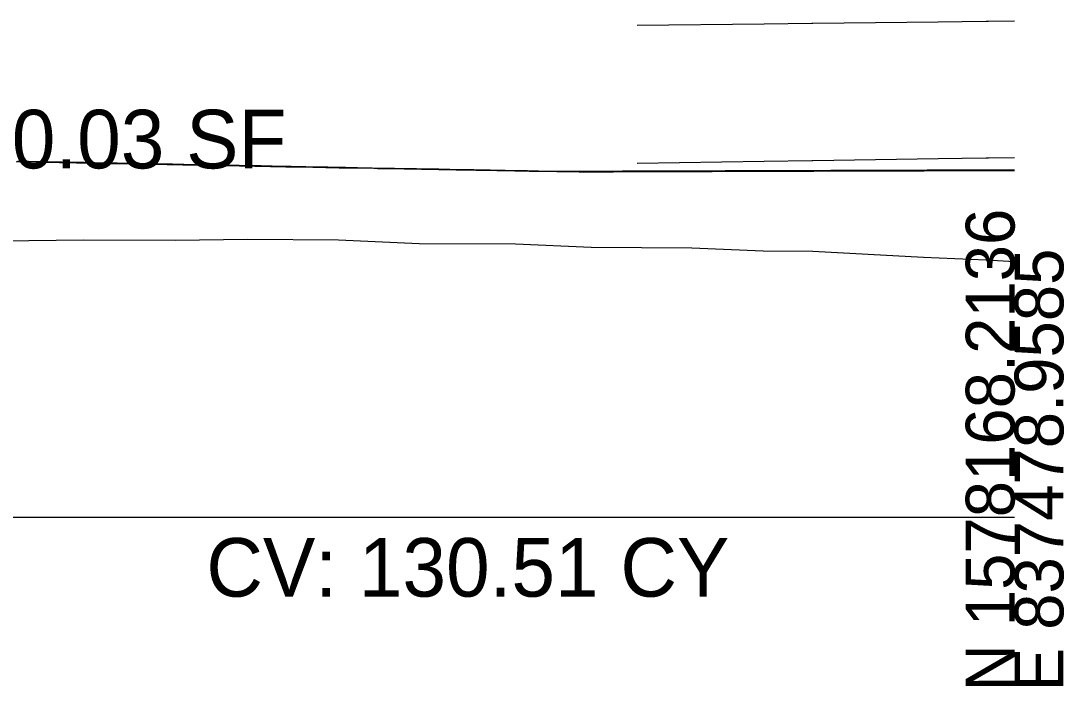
# Model space of a CAD drawing. Extents: x -26 to 303, y -16 to 6048.
# Drawn here: x 243 to 302.8, y 5490.3 to 5528.5 of the extents above; entities that cross this region are included whole.
import ezdxf

# ---------------------------------------------------------------- set-up
doc = ezdxf.new("R2010")
doc.units = 0
for name, color, linetype in [('CONST_LV3', 7, 'Continuous'), ('DTM_P_FINISHED_GRADE2', 7, 'Continuous'), ('DTM_X_GROUND', 7, 'Continuous'), ('XS_CELL', 7, 'Continuous'), ('XS_M_SHAPES_EARTHWORK', 7, 'Continuous'), ('XS_P_GROUND', 7, 'Continuous'), ('XS_SHEET_EW_TX_AREA', 7, 'Continuous'), ('XS_SHEET_EW_TX_VOLUME', 7, 'Continuous')]:
    doc.layers.add(name, color=color, linetype=linetype)

msp = doc.modelspace()

# ---------------------------------------------------------------- linework, layer by layer
at = {"layer": 'CONST_LV3'}
for points in [[(278.373, 5528.214), (285.642, 5528.296), (288.373, 5528.327), (288.404, 5528.327), (288.414, 5528.327), (288.44, 5528.328), (295.619, 5528.411), (298.374, 5528.443), (298.435, 5528.443), (298.455, 5528.444), (298.506, 5528.444), (300, 5528.462)], [(278.373, 5520.307), (285.642, 5520.418), (288.373, 5520.459), (288.404, 5520.46), (288.414, 5520.46), (288.44, 5520.46), (295.619, 5520.569), (298.374, 5520.61), (298.435, 5520.611), (298.455, 5520.611), (298.506, 5520.612), (300, 5520.634)]]:
    msp.add_lwpolyline(points, dxfattribs=at)
at = {"layer": 'DTM_P_FINISHED_GRADE2'}
msp.add_lwpolyline([(243.02, 5520.399), (243.352, 5520.393), (243.522, 5520.39), (243.654, 5520.387), (244.12, 5520.378), (244.289, 5520.375), (244.755, 5520.366), (244.923, 5520.363), (245.391, 5520.354), (245.558, 5520.351), (245.606, 5520.35), (245.624, 5520.35), (246.092, 5520.341), (246.193, 5520.339), (246.328, 5520.336), (246.378, 5520.335), (246.495, 5520.333), (246.779, 5520.328), (246.827, 5520.327), (247.16, 5520.32), (247.324, 5520.317), (247.462, 5520.315), (247.625, 5520.312), (248.097, 5520.303), (248.259, 5520.299), (248.732, 5520.291), (248.893, 5520.287), (249.367, 5520.279), (249.528, 5520.275), (250.001, 5520.267), (250.114, 5520.264), (250.588, 5520.255), (250.636, 5520.255), (250.968, 5520.248), (251.094, 5520.246), (251.238, 5520.243), (251.271, 5520.243), (251.647, 5520.235), (251.806, 5520.232), (251.905, 5520.231), (252.382, 5520.222), (252.54, 5520.219), (253.018, 5520.21), (253.224, 5520.206), (253.857, 5520.194), (253.946, 5520.192), (253.963, 5520.192), (254.07, 5520.19), (254.342, 5520.185), (254.395, 5520.184), (254.727, 5520.177), (254.928, 5520.174), (255.559, 5520.162), (255.744, 5520.158), (256.326, 5520.147), (256.446, 5520.145), (256.83, 5520.138), (257.131, 5520.132), (257.233, 5520.13), (258.203, 5520.112), (258.4, 5520.108), (258.731, 5520.102), (259.027, 5520.096), (259.669, 5520.084), (259.82, 5520.081), (259.852, 5520.081), (259.904, 5520.08), (260.881, 5520.061), (260.94, 5520.06), (261.039, 5520.058), (261.539, 5520.049), (261.735, 5520.045), (261.844, 5520.043), (262.016, 5520.04), (262.211, 5520.036), (262.506, 5520.031), (262.835, 5520.025), (263.482, 5520.013), (263.777, 5520.007), (264.753, 5519.989), (264.851, 5519.987), (264.92, 5519.986), (265.049, 5519.983), (266.024, 5519.965), (266.32, 5519.96), (266.644, 5519.954), (267.293, 5519.942), (267.467, 5519.938), (268.439, 5519.92), (268.562, 5519.918), (269.132, 5519.908), (269.229, 5519.906), (269.426, 5519.902), (269.83, 5519.895), (270.037, 5519.891), (270.358, 5519.885), (270.443, 5519.883), (271.101, 5519.871), (271.393, 5519.866), (272.085, 5519.853), (272.18, 5519.851), (272.466, 5519.846), (272.664, 5519.842), (272.704, 5519.842), (272.956, 5519.843), (273.937, 5519.825), (274.09, 5519.825), (274.407, 5519.82), (274.415, 5519.82), (274.548, 5519.82), (275.21, 5519.808), (275.304, 5519.808), (275.44, 5519.807), (275.642, 5519.808), (276.485, 5519.81), (276.993, 5519.812), (277.019, 5519.812), (277.355, 5519.813), (277.793, 5519.815), (278.103, 5519.816), (278.764, 5519.818), (279.099, 5519.819), (279.122, 5519.819), (279.166, 5519.819), (279.212, 5519.82), (280.301, 5519.823), (280.524, 5519.824), (280.861, 5519.825), (281.954, 5519.829), (281.963, 5519.829), (282.036, 5519.829), (282.179, 5519.829), (282.51, 5519.83), (282.661, 5519.831), (283.383, 5519.833), (283.643, 5519.834), (283.653, 5519.834), (284.737, 5519.838), (284.811, 5519.838), (284.842, 5519.838), (285.189, 5519.839), (286.24, 5519.843), (287.055, 5519.845), (287.406, 5519.846), (287.436, 5519.846), (287.665, 5519.847), (288.016, 5519.848), (289.092, 5519.852), (289.217, 5519.852), (289.234, 5519.852), (289.446, 5519.853), (290.523, 5519.856), (290.881, 5519.857), (291.953, 5519.861), (292.312, 5519.862), (292.689, 5519.863), (292.74, 5519.863), (292.743, 5519.863), (293.381, 5519.865), (293.708, 5519.866), (294.77, 5519.87), (294.809, 5519.87), (295.178, 5519.871), (296.229, 5519.874), (296.48, 5519.875), (296.488, 5519.875), (296.608, 5519.876), (297.552, 5519.879), (297.665, 5519.879), (298.039, 5519.88), (299.094, 5519.883), (299.27, 5519.884), (299.472, 5519.884), (300, 5519.886)], dxfattribs=at)
at = {"layer": 'DTM_X_GROUND'}
for points in [[(243.02, 5520.399), (243.352, 5520.393), (243.49, 5520.39), (243.535, 5520.389), (243.622, 5520.388), (243.654, 5520.387), (244.032, 5520.38), (244.17, 5520.377), (244.257, 5520.376), (244.289, 5520.375), (244.668, 5520.368), (244.804, 5520.365), (244.892, 5520.363), (244.923, 5520.363), (245.303, 5520.356), (245.439, 5520.353), (245.527, 5520.351), (245.558, 5520.351), (245.606, 5520.35), (245.987, 5520.343), (246.005, 5520.342), (246.074, 5520.341), (246.162, 5520.339), (246.193, 5520.339), (246.328, 5520.336), (246.378, 5520.335), (246.495, 5520.333), (246.691, 5520.329), (246.708, 5520.329), (246.796, 5520.327), (246.827, 5520.327), (247.16, 5520.32), (247.293, 5520.318), (247.343, 5520.317), (247.431, 5520.315), (247.462, 5520.315), (247.595, 5520.312), (247.771, 5520.309), (247.978, 5520.305), (248.008, 5520.304), (248.14, 5520.302), (248.229, 5520.3), (248.259, 5520.299), (248.643, 5520.292), (248.775, 5520.29), (248.863, 5520.288), (248.893, 5520.287), (249.278, 5520.28), (249.409, 5520.278), (249.498, 5520.276), (249.528, 5520.275), (249.913, 5520.268), (250.025, 5520.266), (250.114, 5520.264), (250.358, 5520.26), (250.499, 5520.257), (250.518, 5520.257), (250.606, 5520.255), (250.636, 5520.255), (250.968, 5520.248), (251.094, 5520.246), (251.149, 5520.245), (251.238, 5520.243), (251.241, 5520.243), (251.271, 5520.243), (251.647, 5520.235), (251.776, 5520.233), (251.787, 5520.233), (251.876, 5520.231), (251.905, 5520.231), (251.946, 5520.23), (252.334, 5520.223), (252.409, 5520.221), (252.498, 5520.219), (252.54, 5520.219), (252.663, 5520.216), (252.89, 5520.212), (253.097, 5520.208), (253.224, 5520.206), (253.289, 5520.205), (253.921, 5520.193), (253.946, 5520.192), (253.963, 5520.192), (254.07, 5520.19), (254.268, 5520.186), (254.342, 5520.185), (254.395, 5520.184), (254.556, 5520.181), (254.888, 5520.174), (254.928, 5520.174), (255.431, 5520.164), (255.615, 5520.161), (255.744, 5520.158), (255.824, 5520.157), (256.406, 5520.146), (256.446, 5520.145), (256.623, 5520.142), (256.701, 5520.14), (256.963, 5520.135), (257.092, 5520.133), (257.131, 5520.132), (257.233, 5520.13), (258.074, 5520.114), (258.231, 5520.111), (258.36, 5520.109), (258.4, 5520.108), (258.731, 5520.102), (259.242, 5520.092), (259.5, 5520.087), (259.539, 5520.087), (259.583, 5520.086), (259.669, 5520.084), (259.82, 5520.081), (259.852, 5520.081), (259.904, 5520.08), (260.751, 5520.064), (260.771, 5520.063), (260.81, 5520.063), (260.909, 5520.061), (261.039, 5520.058), (261.195, 5520.055), (261.696, 5520.046), (261.804, 5520.044), (261.844, 5520.043), (262.016, 5520.04), (262.081, 5520.039), (262.211, 5520.036), (262.467, 5520.032), (262.795, 5520.025), (262.835, 5520.025), (263.352, 5520.015), (263.482, 5520.013), (263.738, 5520.008), (264.584, 5519.992), (264.623, 5519.991), (264.722, 5519.989), (264.851, 5519.987), (264.92, 5519.986), (265.01, 5519.984), (265.855, 5519.968), (265.894, 5519.968), (266.024, 5519.965), (266.281, 5519.96), (266.605, 5519.954), (267.125, 5519.945), (267.254, 5519.942), (267.293, 5519.942), (268.136, 5519.926), (268.31, 5519.923), (268.393, 5519.921), (268.522, 5519.919), (268.562, 5519.918), (269.132, 5519.908), (269.229, 5519.906), (269.493, 5519.901), (269.503, 5519.901), (269.661, 5519.898), (269.7, 5519.897), (269.83, 5519.895), (270.037, 5519.891), (270.358, 5519.885), (270.404, 5519.884), (270.443, 5519.883), (270.971, 5519.874), (271.101, 5519.871), (271.354, 5519.866), (272.046, 5519.854), (272.085, 5519.853), (272.18, 5519.851), (272.336, 5519.848), (272.466, 5519.846), (272.625, 5519.843), (272.918, 5519.843), (273.767, 5519.827), (273.806, 5519.827), (273.937, 5519.825), (274.09, 5519.825), (274.407, 5519.82), (274.415, 5519.82), (274.509, 5519.82), (275.04, 5519.81), (275.08, 5519.81), (275.174, 5519.811), (275.304, 5519.808), (275.44, 5519.807), (275.602, 5519.807), (275.614, 5519.808), (275.626, 5519.808), (275.642, 5519.808), (276.355, 5519.81), (276.993, 5519.812), (277.019, 5519.812), (277.339, 5519.813), (277.648, 5519.814), (277.777, 5519.815), (277.793, 5519.815), (278.103, 5519.816), (278.634, 5519.818), (278.954, 5519.819), (278.993, 5519.819), (279.032, 5519.819), (279.083, 5519.819), (279.099, 5519.819), (279.122, 5519.819), (279.166, 5519.819), (279.212, 5519.82), (279.952, 5519.822), (280.249, 5519.823), (280.456, 5519.824), (280.472, 5519.824), (280.524, 5519.824), (280.845, 5519.825), (281.886, 5519.828), (281.902, 5519.828), (281.911, 5519.828), (281.963, 5519.829), (282.036, 5519.829), (282.179, 5519.829), (282.494, 5519.83), (282.644, 5519.831), (283.315, 5519.833), (283.331, 5519.833), (283.383, 5519.833), (283.643, 5519.834), (283.653, 5519.834), (284.686, 5519.838), (284.743, 5519.838), (284.76, 5519.838), (284.811, 5519.838), (284.842, 5519.838), (285.172, 5519.839), (286.172, 5519.842), (286.189, 5519.842), (286.24, 5519.843), (286.604, 5519.844), (287.055, 5519.845), (287.39, 5519.846), (287.42, 5519.846), (287.597, 5519.847), (287.648, 5519.847), (287.665, 5519.847), (287.999, 5519.848), (288.495, 5519.85), (289.024, 5519.852), (289.041, 5519.852), (289.165, 5519.852), (289.182, 5519.852), (289.234, 5519.852), (289.429, 5519.853), (289.446, 5519.853), (290.472, 5519.856), (290.813, 5519.857), (290.864, 5519.857), (290.881, 5519.857), (291.787, 5519.86), (291.902, 5519.861), (291.953, 5519.861), (292.298, 5519.862), (292.674, 5519.863), (292.726, 5519.863), (292.74, 5519.863), (292.743, 5519.863), (293.33, 5519.865), (293.381, 5519.865), (293.708, 5519.866), (294.719, 5519.87), (294.741, 5519.87), (294.759, 5519.87), (294.809, 5519.87), (295.16, 5519.871), (296.169, 5519.874), (296.187, 5519.874), (296.438, 5519.875), (296.48, 5519.875), (296.488, 5519.875), (296.591, 5519.876), (297.534, 5519.879), (297.552, 5519.879), (297.614, 5519.879), (297.665, 5519.879), (298.021, 5519.88), (298.039, 5519.88), (298.455, 5519.881), (299.043, 5519.883), (299.22, 5519.884), (299.27, 5519.884), (299.454, 5519.884), (299.472, 5519.884), (300, 5519.886)], [(241.923, 5515.837), (246.661, 5515.911), (251.903, 5515.878), (256.032, 5515.945), (261.262, 5515.911), (265.874, 5515.702), (271.39, 5515.668), (275.729, 5515.48), (281.51, 5515.447), (285.595, 5515.276), (288.446, 5515.261), (294.782, 5514.904), (298.379, 5514.755), (300, 5514.662)]]:
    msp.add_lwpolyline(points, dxfattribs=at)
at = {"layer": 'XS_CELL'}
msp.add_line((150, 5500), (300, 5500), dxfattribs=at)
at = {"layer": 'XS_M_SHAPES_EARTHWORK'}
for points in [[(272.625, 5519.843), (272.918, 5519.843), (273.767, 5519.827), (273.806, 5519.827), (273.937, 5519.825), (274.09, 5519.825), (274.407, 5519.82), (274.415, 5519.82), (274.509, 5519.82), (275.04, 5519.81), (275.08, 5519.81), (275.174, 5519.811), (275.304, 5519.808), (275.44, 5519.807), (274.793, 5519.805), (274.617, 5519.806), (273.758, 5519.822), (273.347, 5519.83), (272.625, 5519.843)], [(275.44, 5519.807), (275.602, 5519.807), (275.614, 5519.808), (275.626, 5519.808), (275.642, 5519.808), (276.355, 5519.81), (276.993, 5519.812), (277.019, 5519.812), (277.339, 5519.813), (277.648, 5519.814), (277.777, 5519.815), (277.793, 5519.815), (278.103, 5519.816), (278.634, 5519.818), (278.954, 5519.819), (278.993, 5519.819), (279.032, 5519.819), (279.083, 5519.819), (279.099, 5519.819), (279.122, 5519.819), (279.166, 5519.819), (279.212, 5519.82), (279.952, 5519.822), (280.249, 5519.823), (280.456, 5519.824), (280.472, 5519.824), (280.524, 5519.824), (280.845, 5519.825), (281.886, 5519.828), (281.902, 5519.828), (281.911, 5519.828), (281.963, 5519.829), (282.036, 5519.829), (282.179, 5519.829), (282.494, 5519.83), (282.644, 5519.831), (283.315, 5519.833), (283.331, 5519.833), (283.383, 5519.833), (283.643, 5519.834), (283.653, 5519.834), (284.686, 5519.838), (284.743, 5519.838), (284.76, 5519.838), (284.811, 5519.838), (284.842, 5519.838), (285.172, 5519.839), (286.172, 5519.842), (286.189, 5519.842), (286.24, 5519.843), (286.604, 5519.844), (287.055, 5519.845), (287.39, 5519.846), (287.42, 5519.846), (287.597, 5519.847), (287.648, 5519.847), (287.665, 5519.847), (287.999, 5519.848), (288.495, 5519.85), (289.024, 5519.852), (289.041, 5519.852), (289.165, 5519.852), (289.182, 5519.852), (289.234, 5519.852), (289.429, 5519.853), (289.446, 5519.853), (290.472, 5519.856), (290.813, 5519.857), (290.864, 5519.857), (290.881, 5519.857), (291.787, 5519.86), (291.902, 5519.861), (291.953, 5519.861), (292.298, 5519.862), (292.674, 5519.863), (292.726, 5519.863), (292.74, 5519.863), (292.743, 5519.863), (293.33, 5519.865), (293.381, 5519.865), (293.708, 5519.866), (294.719, 5519.87), (294.741, 5519.87), (294.759, 5519.87), (294.809, 5519.87), (295.16, 5519.871), (296.169, 5519.874), (296.187, 5519.874), (296.438, 5519.875), (296.48, 5519.875), (296.488, 5519.875), (296.591, 5519.876), (297.534, 5519.879), (297.552, 5519.879), (297.614, 5519.879), (297.665, 5519.879), (298.021, 5519.88), (298.039, 5519.88), (298.455, 5519.881), (299.043, 5519.883), (299.22, 5519.884), (299.27, 5519.884), (299.454, 5519.884), (299.472, 5519.884), (300, 5519.886), (299.756, 5519.885), (299.295, 5519.884), (298.334, 5519.881), (296.913, 5519.877), (296.761, 5519.876), (295.491, 5519.872), (295.48, 5519.872), (294.069, 5519.868), (292.648, 5519.863), (291.795, 5519.86), (291.726, 5519.86), (291.226, 5519.859), (289.804, 5519.854), (288.382, 5519.849), (286.96, 5519.845), (286.657, 5519.844), (286.617, 5519.844), (285.538, 5519.84), (284.156, 5519.836), (284.116, 5519.836), (282.694, 5519.831), (281.75, 5519.828), (281.554, 5519.827), (281.367, 5519.827), (281.271, 5519.826), (279.849, 5519.822), (278.427, 5519.817), (277.562, 5519.814), (277.157, 5519.813), (276.584, 5519.811), (276.55, 5519.811), (275.887, 5519.808), (275.44, 5519.807)]]:
    msp.add_lwpolyline(points, close=True, dxfattribs=at)
at = {"layer": 'XS_P_GROUND'}
for points in [[(242.779, 5520.391), (243.136, 5520.384), (243.325, 5520.381), (248.171, 5520.289), (251.429, 5520.227), (253.205, 5520.194), (255.582, 5520.149), (258.238, 5520.099), (258.621, 5520.092), (259.018, 5520.084), (261.294, 5520.042), (263.272, 5520.005), (263.497, 5520), (264.021, 5519.991), (267.997, 5519.917), (268.306, 5519.911), (269.267, 5519.894), (272.463, 5519.835), (273.335, 5519.838), (273.34, 5519.838), (273.358, 5519.838), (273.433, 5519.838), (273.503, 5519.838), (273.506, 5519.838), (274.522, 5519.842), (275.076, 5519.844), (275.551, 5519.845), (276.491, 5519.849), (276.603, 5519.849), (276.723, 5519.849), (276.726, 5519.849), (277.188, 5519.851), (277.197, 5519.851), (277.536, 5519.852), (278.373, 5519.855), (278.653, 5519.856), (279.523, 5519.859), (279.676, 5519.859), (279.88, 5519.86), (280.727, 5519.863), (280.96, 5519.863), (282.774, 5519.869), (282.841, 5519.87), (282.862, 5519.87), (282.868, 5519.87), (282.87, 5519.87), (283.407, 5519.871), (283.454, 5519.872), (283.454, 5519.872), (283.511, 5519.872), (283.523, 5519.872), (284.148, 5519.874), (284.228, 5519.874), (284.727, 5519.876), (285.294, 5519.878), (286.383, 5519.881), (288.44, 5519.888), (288.485, 5519.888), (288.487, 5519.888), (288.554, 5519.888), (288.554, 5519.888), (288.567, 5519.888), (288.588, 5519.888), (289.466, 5519.891), (289.518, 5519.891), (289.682, 5519.892), (289.73, 5519.892), (289.843, 5519.892), (290.083, 5519.893), (290.459, 5519.894), (292.219, 5519.9), (292.312, 5519.9), (292.314, 5519.9), (292.346, 5519.901), (292.424, 5519.901), (292.84, 5519.902), (293.189, 5519.903), (293.296, 5519.904), (293.473, 5519.904), (294.184, 5519.906), (294.485, 5519.907), (294.996, 5519.909), (295.014, 5519.909), (295.027, 5519.909), (295.034, 5519.909), (295.038, 5519.909), (295.643, 5519.911), (295.759, 5519.911), (295.995, 5519.912), (296.013, 5519.912), (296.032, 5519.912), (298.507, 5519.92), (299.433, 5519.923), (300, 5519.925)], [(300, 5519.886), (299.756, 5519.885), (299.295, 5519.884), (298.334, 5519.881), (296.913, 5519.877), (296.761, 5519.876), (295.491, 5519.872), (295.48, 5519.872), (294.069, 5519.868), (292.648, 5519.863), (291.795, 5519.86), (291.726, 5519.86), (291.226, 5519.859), (289.804, 5519.854), (288.382, 5519.849), (286.96, 5519.845), (286.657, 5519.844), (286.617, 5519.844), (285.538, 5519.84), (284.156, 5519.836), (284.116, 5519.836), (282.694, 5519.831), (281.75, 5519.828), (281.554, 5519.827), (281.367, 5519.827), (281.271, 5519.826), (279.849, 5519.822), (278.427, 5519.817), (277.562, 5519.814), (277.157, 5519.813), (276.584, 5519.811), (276.55, 5519.811), (275.887, 5519.808), (274.793, 5519.805), (274.617, 5519.806), (273.758, 5519.822), (273.347, 5519.83), (272.076, 5519.853), (271.705, 5519.86), (270.806, 5519.877), (269.952, 5519.892), (269.536, 5519.9), (269.01, 5519.91), (268.266, 5519.924), (266.995, 5519.947), (266.439, 5519.957), (266.147, 5519.963), (265.725, 5519.971), (264.454, 5519.994), (263.184, 5520.018), (262.34, 5520.034), (261.913, 5520.042), (261.659, 5520.047), (261.435, 5520.051), (261.293, 5520.054), (260.642, 5520.066), (259.372, 5520.09), (258.534, 5520.105), (258.101, 5520.114), (256.83, 5520.138), (256.326, 5520.147), (255.559, 5520.162), (254.727, 5520.177), (254.289, 5520.186), (254.218, 5520.187), (253.857, 5520.194), (253.018, 5520.21), (252.382, 5520.222), (251.747, 5520.234), (251.614, 5520.236), (251.111, 5520.246), (250.919, 5520.249), (250.476, 5520.258), (249.84, 5520.27), (249.205, 5520.282), (248.569, 5520.294), (247.933, 5520.306), (247.298, 5520.318), (247.111, 5520.321), (246.662, 5520.33), (246.278, 5520.337), (246.209, 5520.338), (246.027, 5520.342), (245.391, 5520.354), (244.755, 5520.366), (244.12, 5520.378), (243.484, 5520.39), (243.303, 5520.394), (242.848, 5520.402)]]:
    msp.add_lwpolyline(points, dxfattribs=at)

# ---------------------------------------------------------------- texts
at = {"layer": 'XS_CELL'}
for s, p in [('N 1578168.2136', (300, 5490)), ('E 837478.9585', (302.8, 5490))]:
    msp.add_text(s, height=2.8, rotation=90, dxfattribs=at).set_placement(p)
at = {"layer": 'XS_SHEET_EW_TX_AREA'}
msp.add_text('CA: 170.03 SF', height=3.36, dxfattribs=at).set_placement((228.794, 5520))
at = {"layer": 'XS_SHEET_EW_TX_VOLUME'}
msp.add_text('CV: 130.51 CY', height=3.36, dxfattribs=at).set_placement((253.681, 5495.44))

doc.saveas('drawing.dxf')
